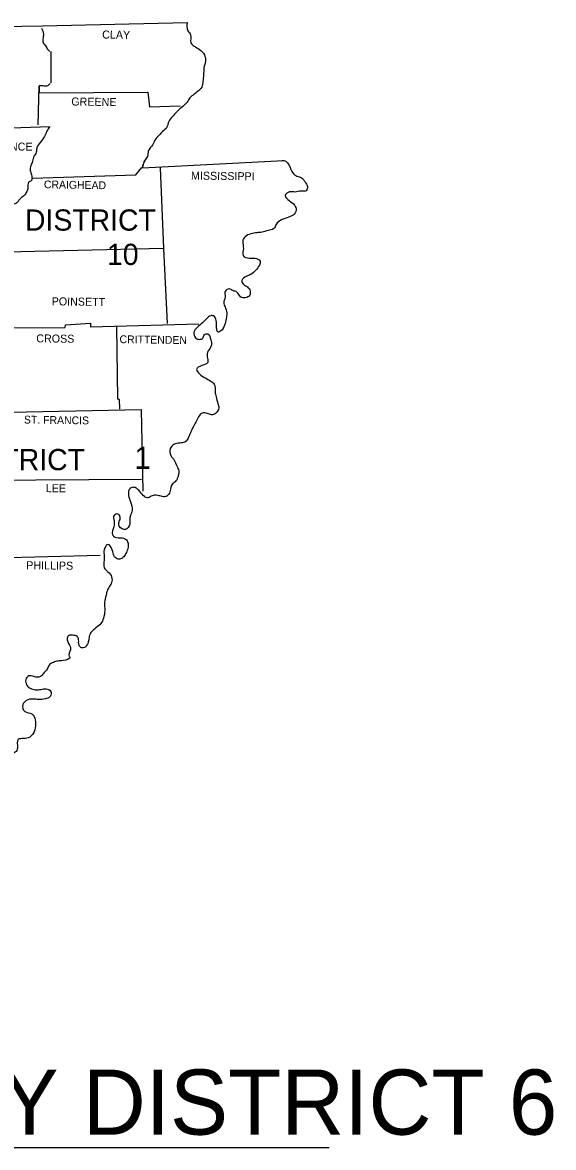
# Model space of a CAD drawing. Extents: x -42408 to 34530, y -43140 to 20491.
# Drawn here: x -15135 to -13565, y 2539 to 5867 of the extents above; entities that cross this region are included whole.
import ezdxf

# ---------------------------------------------------------------- set-up
doc = ezdxf.new("R2010")
doc.units = 0
for name, color, linetype in [('1', 7, 'Continuous'), ('2', 7, 'Continuous'), ('3', 7, 'Continuous')]:
    doc.layers.add(name, color=color, linetype=linetype)

msp = doc.modelspace()

# ---------------------------------------------------------------- linework, layer by layer
at = {"layer": '1'}
for p, q in [((-14780.6, 5436.9), (-14774, 5457.3)), ((-14779, 5443.5), (-14772.4, 5459.5)), ((-17741.9, 2539.3), (-14228.8, 2539.3))]:
    msp.add_line(p, q, dxfattribs=at)
for points in [[(-17667.8, 5841.4), (-16777.9, 5840.9), (-15996.9, 5842.5), (-15075.6, 5856.8), (-14648.6, 5866.7)], [(-15051.4, 5780.9), (-15051.4, 5687.9)], [(-15088.8, 5564.1), (-15086.1, 5679.1), (-15086.1, 5658.7), (-14764.1, 5660.4), (-14759.7, 5617.4), (-14668.9, 5620.7)], [(-15257.3, 5551.9), (-15053.1, 5559.1)], [(-14780.6, 5436.9), (-14362.9, 5458.4)], [(-15105.4, 5406.7), (-14799.9, 5416.6), (-14781.7, 5437.5)], [(-14727.8, 5436.4), (-14718.5, 5198.1), (-14707.4, 4976.3)], [(-14718.5, 5198.1), (-15225.3, 5186.5)], [(-15220.9, 4963.6), (-15008.5, 4964.7), (-15007.9, 4972.4), (-14934.2, 4977.9), (-14934.2, 4966.4), (-14613.9, 4975.2)], [(-14857.1, 4966.4), (-14854.4, 4754.5), (-14849.4, 4751.2), (-14847.8, 4722.6)], [(-15220.9, 4713.2), (-14783.9, 4722)], [(-14783.9, 4722), (-14779.5, 4481)], [(-15220.9, 4025.3), (-15178, 4028), (-15178.6, 4139.7), (-15218.7, 4142.5), (-15216.5, 4361), (-15251.2, 4365.9), (-15252.3, 4512.9), (-14782.8, 4516.2)], [(-15215.4, 4283.4), (-14905, 4291.1)]]:
    msp.add_lwpolyline(points, dxfattribs=at)
for points in [[(-14648.6, 5866.7), (-14645.8, 5842.5), (-14638.1, 5829.9), (-14637, 5806.8), (-14627.6, 5796.9), (-14611.7, 5786.9), (-14597.4, 5771), (-14594.1, 5752.3), (-14598.5, 5733), (-14599.6, 5711.5), (-14601.8, 5692.8), (-14605.1, 5675.8), (-14618.3, 5662), (-14630.9, 5652.1), (-14642.5, 5640.6), (-14650.8, 5628.4), (-14665.1, 5615.2), (-14679.4, 5601.5), (-14690.9, 5589.4), (-14702.5, 5574), (-14708, 5556.9), (-14720.7, 5544.8), (-14730.6, 5533.8), (-14743.8, 5518.9), (-14750.4, 5504.1), (-14763, 5487), (-14765.8, 5470.5), (-14774, 5457.3), (-14774.6, 5455.1)], [(-15078.4, 5849.7), (-15073.4, 5835.9), (-15074, 5821.1), (-15074, 5807.3), (-15066.8, 5798), (-15059.7, 5786.4), (-15054.2, 5781.4)], [(-15053.6, 5686.2), (-15060.8, 5679.1), (-15074.5, 5679.1), (-15086.1, 5679.1)], [(-15054.7, 5558.5), (-15063, 5545.3), (-15069.6, 5529.9), (-15082.8, 5512.3), (-15092.7, 5495.3), (-15094.3, 5483.7), (-15102.1, 5468.3), (-15106.5, 5452.9), (-15111.4, 5439.7), (-15111.4, 5425.9), (-15107.6, 5412.2), (-15108.7, 5399.5), (-15116.9, 5393.4), (-15119.1, 5377.5), (-15122.4, 5366.5), (-15129.6, 5355.5), (-15140, 5347.2), (-15151, 5334.6), (-15159.3, 5329.1)], [(-14369, 5457.8), (-14362.9, 5458.4), (-14344.2, 5438.6), (-14336, 5422.1), (-14323.9, 5412.7), (-14310.1, 5407.8), (-14299.6, 5395.1), (-14292.5, 5381.3), (-14296.3, 5369.2), (-14311.7, 5368.1), (-14328.8, 5365.4), (-14345.3, 5365.9), (-14358.5, 5354.9), (-14346.4, 5340.1), (-14330.5, 5326.3), (-14326.1, 5311.4), (-14334.9, 5297.1), (-14352.5, 5289.4), (-14369.5, 5282.8), (-14384.9, 5269.6), (-14392.1, 5257), (-14409.2, 5251.5), (-14426.8, 5246.5), (-14442.2, 5244.8), (-14459.8, 5241.5), (-14476.9, 5233.3), (-14484, 5219), (-14481.8, 5198.6), (-14482.4, 5177.2), (-14464.2, 5170), (-14448.2, 5169.4), (-14432.8, 5161.2), (-14434.5, 5149.1), (-14446, 5133.7), (-14459.8, 5121.6), (-14473.5, 5115.5), (-14486.2, 5104), (-14481.8, 5092.4), (-14470.2, 5084.7), (-14462, 5072), (-14463.1, 5060.5), (-14476.3, 5052.2), (-14490.6, 5055.5), (-14501.1, 5069.3), (-14513.2, 5073.7), (-14523.6, 5078.6), (-14535.7, 5071.5), (-14535.7, 5055.5), (-14540.1, 5038.5), (-14536.3, 5025.8), (-14531.3, 5008.2), (-14531.9, 4995), (-14536.3, 4976.3), (-14545.6, 4957), (-14556.7, 4951), (-14561.1, 4971.9), (-14563.3, 4988.9), (-14569.9, 4998.8), (-14578.7, 4999.4), (-14590.2, 4991.1), (-14602.9, 4978.5), (-14618.8, 4964.7), (-14628.2, 4951), (-14623.2, 4933.9), (-14611.1, 4929.5), (-14601.8, 4932.8), (-14596.8, 4943.8), (-14587.5, 4945.5), (-14578.7, 4928.4)], [(-14578.7, 4928.4), (-14576.5, 4912.4), (-14585.8, 4895.4), (-14589.1, 4878.3), (-14587.5, 4861.2), (-14605.1, 4851.9), (-14620.5, 4840.9), (-14611.7, 4827.7), (-14595.2, 4815.6), (-14578.7, 4806.2), (-14568.2, 4796.9), (-14565.5, 4774.3), (-14562.7, 4760), (-14557.2, 4740.2), (-14555, 4726.4), (-14564.9, 4709.9), (-14576.5, 4706.6), (-14588.6, 4710.5), (-14602.9, 4711.6), (-14614.4, 4700.5), (-14622.7, 4685.1), (-14630.9, 4669.7), (-14637, 4656.5), (-14643.1, 4642.2), (-14655.2, 4625.7), (-14670, 4622.9), (-14687.6, 4618.5), (-14698.1, 4606.4), (-14696.4, 4586.1), (-14686.5, 4572.3), (-14678.8, 4555.3), (-14673.3, 4540.4), (-14676.1, 4521.7), (-14683.8, 4507.9), (-14693.7, 4499.7), (-14698.1, 4482.1), (-14705.2, 4468.8), (-14711.9, 4464.4), (-14725.1, 4465.5), (-14739.4, 4468.3), (-14751.5, 4467.2), (-14763, 4461.1), (-14774.6, 4465), (-14786.7, 4478.2), (-14796.6, 4488.1), (-14807.6, 4492), (-14819.2, 4485.9), (-14821.4, 4467.7), (-14815.9, 4449), (-14810.9, 4423.7), (-14815.9, 4408.3), (-14817.5, 4383)], [(-14817.5, 4383), (-14830.2, 4367), (-14848.9, 4376.9), (-14848.9, 4390.1), (-14846.1, 4403.9), (-14852.7, 4412.7), (-14864.3, 4408.9), (-14864.3, 4391.8), (-14865.4, 4375.3), (-14868.7, 4351.6), (-14861, 4344.5), (-14843.4, 4342.3), (-14830.7, 4339), (-14823, 4326.3), (-14823.6, 4310.9), (-14829.6, 4296), (-14838.4, 4283.9), (-14852.2, 4279.5), (-14863.2, 4286.7), (-14867.6, 4301), (-14872.6, 4313.6), (-14881.9, 4323), (-14891.8, 4312.5), (-14894, 4293.3), (-14893.5, 4276.8), (-14893.5, 4254.2), (-14879.2, 4239.3), (-14870.4, 4222.3), (-14873.1, 4206.9), (-14883.6, 4188.7), (-14888, 4172.8), (-14892.4, 4151.3), (-14891.8, 4127.6), (-14895.7, 4104.5), (-14903.4, 4089.1), (-14917.7, 4076.4), (-14927, 4068.2), (-14934.7, 4059.9), (-14938.6, 4043.4), (-14941.3, 4031.9), (-14951.8, 4018.1), (-14960.1, 4017), (-14966.7, 4022.5), (-14968.9, 4031.9), (-14968.9, 4041.2), (-14973.3, 4050.6), (-14987, 4054.4), (-14998, 4053.9), (-15003, 4046.2), (-14995.8, 4024.7), (-14993.1, 4011), (-14996.9, 3992.2), (-14994.7, 3990), (-15014.5, 3979.6), (-15030.5, 3977.9), (-15043.7, 3974.1), (-15056.4, 3965.8), (-15062.4, 3953.7), (-15071.2, 3943.8), (-15078.9, 3934.5), (-15089.4, 3930.1), (-15101, 3932.3), (-15116.4, 3933.9), (-15125.2, 3922.9), (-15122.4, 3906.9), (-15112, 3897.6), (-15096.5, 3893.2), (-15080.6, 3894.3), (-15065.2, 3895.9), (-15050.9, 3888.2), (-15053.6, 3873.4), (-15067.4, 3866.2), (-15087.7, 3864), (-15104.3, 3865.7), (-15124.1, 3861.3), (-15134, 3848.6), (-15128.5, 3829.3), (-15107, 3821.6), (-15097.1, 3803.5), (-15096.5, 3786.4), (-15103.7, 3763.8), (-15113.6, 3753.4), (-15132.9, 3749), (-15147.7, 3746.2), (-15149.9, 3720.9), (-15156.5, 3708.3), (-15168.1, 3704.4), (-15184.6, 3712.7), (-15194.5, 3716.5), (-15206.6, 3722), (-15222, 3731.4), (-15233.6, 3729.7), (-15230.3, 3705.5), (-15229.2, 3704.4), (-15216, 3686.2), (-15202.8, 3671.9), (-15196.7, 3654.9)]]:
    msp.add_spline(points, degree=3, dxfattribs=at)

# ---------------------------------------------------------------- texts
msp.add_text('1', height=66, dxfattribs=at).set_placement((-14804.3, 4546.4))
at = {"layer": '2'}
for s, height, rotation, p in [('CLAY', 23.66, 359.2258, (-14899.5, 5819.4)), ('GREENE', 23.67, 359.2361, (-14990.9, 5621.3)), ('LAWRENCE', 23.67, 359.2678, (-15284.8, 5489.8)), ('MISSISSIPPI', 23.66, 359.3097, (-14637, 5402.2)), ('CRAIGHEAD', 23.11, 359.1159, (-15071.8, 5376.4)), ('POINSETT', 23.66, 359.1987, (-15048.8, 5030.4)), ('CROSS', 23.66, 359.3839, (-15094.3, 4920.7)), ('CRITTENDEN', 23.11, 359.213, (-14848.3, 4918.5)), ('ST. FRANCIS', 23.108, 359.2216, (-15130.7, 4680.7)), ('LEE', 23.67, 359.4327, (-15066.3, 4477.7)), ('PHILLIPS', 23.66, 359.3179, (-15124.1, 4249.8))]:
    msp.add_text(s, height=height, rotation=rotation, dxfattribs=at).set_placement(p)
msp.add_text('ARKANSAS HIGHWAY DISTRICT 6', height=192.623, dxfattribs=at).set_placement((-17733.2, 2577.3))
at = {"layer": '3'}
for s, p in [('DISTRICT', (-15127.6, 5251.1)), ('10', (-14885.1, 5149.6)), ('DISTRICT', (-15337.1, 4542.6))]:
    msp.add_text(s, height=62.74, dxfattribs=at).set_placement(p)

doc.saveas('drawing.dxf')
